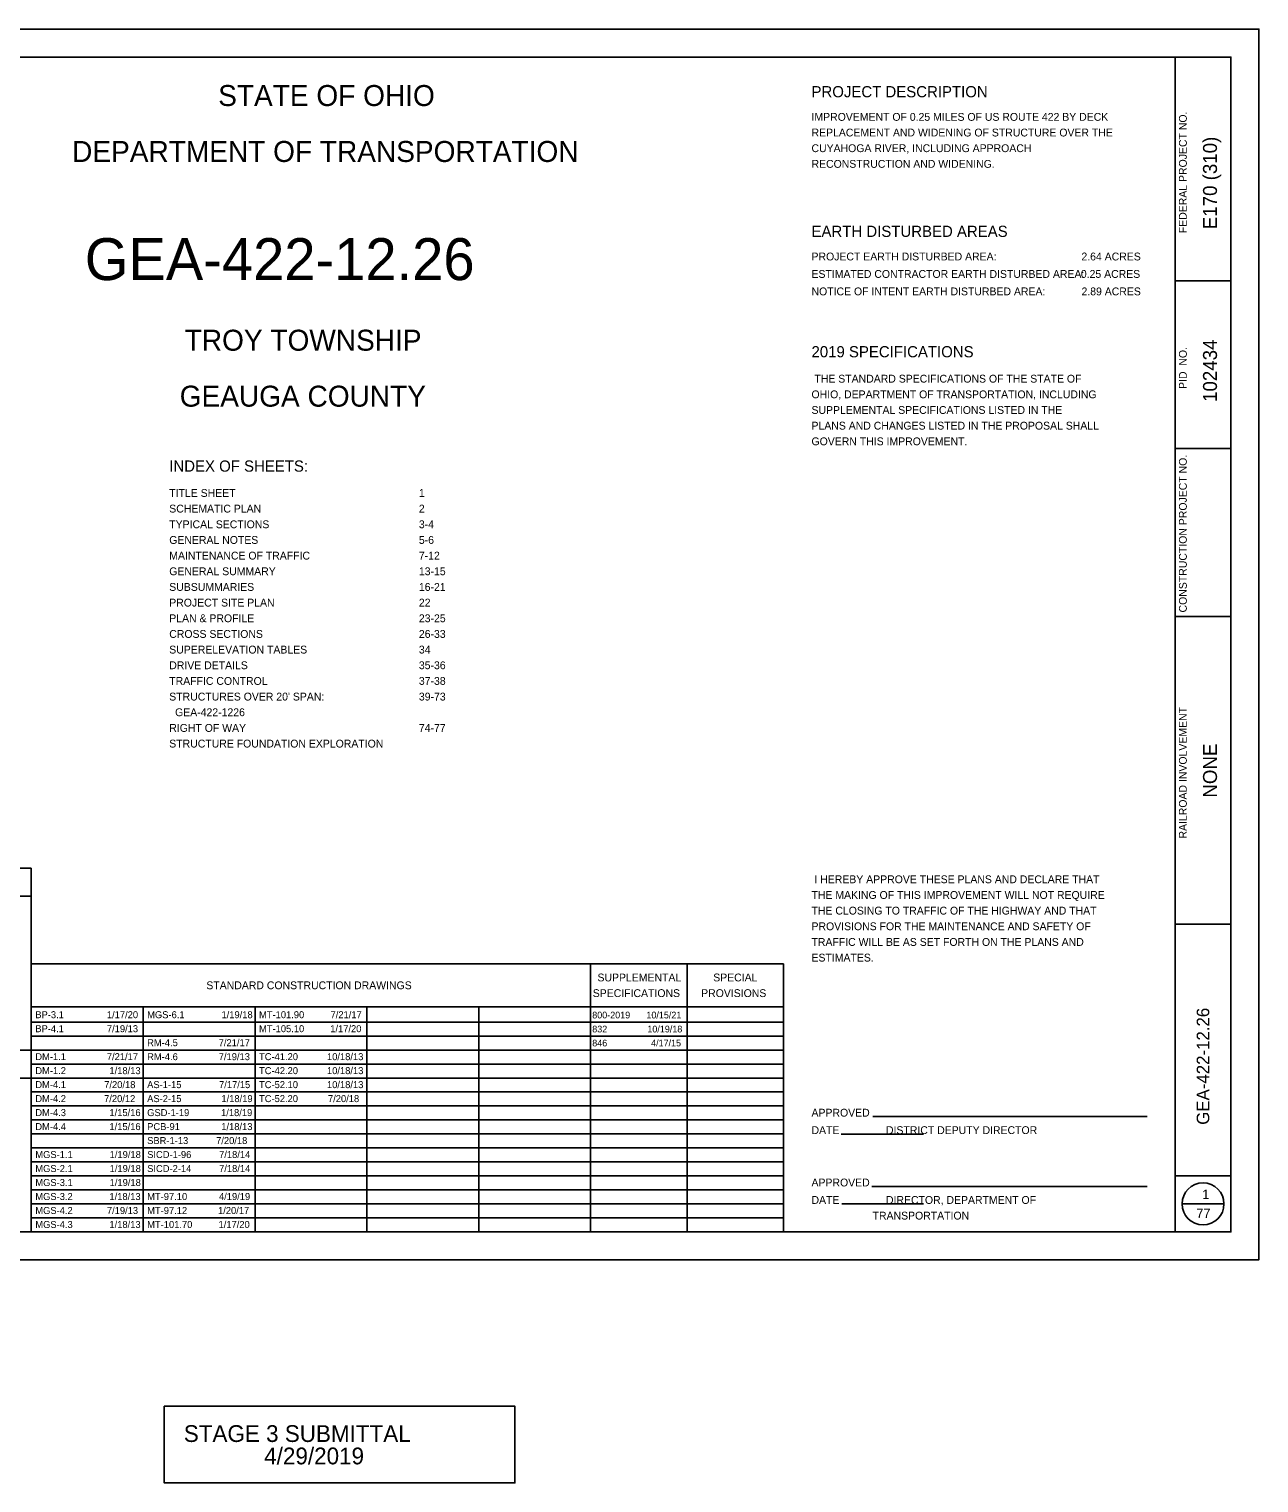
# Model space of a CAD drawing. Extents: x 10.6 to 44.6, y -2.6 to 23.4.
# Drawn here: x 22.61 to 44.6, y -2.56 to 23.43 of the extents above; entities that cross this region are included whole.
import ezdxf

# ---------------------------------------------------------------- set-up
doc = ezdxf.new("R2010")
doc.units = 0
for name, color, linetype in [('SH_Border', 7, 'Continuous'), ('SH_Cut_Line', 7, 'Continuous'), ('SH_Data', 7, 'Continuous'), ('SH_Text', 7, 'Continuous')]:
    doc.layers.add(name, color=color, linetype=linetype)

msp = doc.modelspace()

# ---------------------------------------------------------------- linework, layer by layer
at = {"layer": 'SH_Border'}
for p, q in [((43.103, 1.926), (43.103, 22.926)), ((43.103, 18.926), (44.103, 18.926)), ((43.103, 15.926), (44.103, 15.926)), ((43.103, 12.926), (44.103, 12.926)), ((43.103, 7.426), (44.103, 7.426)), ((43.103, 2.926), (44.103, 2.926))]:
    msp.add_line(p, q, dxfattribs=at)
msp.add_lwpolyline([(12.603, 22.926), (44.103, 22.926), (44.103, 1.926), (12.603, 1.926)], close=True, dxfattribs=at)
at = {"layer": 'SH_Cut_Line'}
msp.add_lwpolyline([(10.603, 1.426), (44.603, 1.426), (44.603, 23.426), (10.603, 23.426)], close=True, dxfattribs=at)
at = {"layer": 'SH_Data'}
for p, q in [((19.853, 8.426), (22.653, 8.426)), ((22.653, 1.926), (22.653, 8.426)), ((19.853, 7.926), (22.653, 7.926)), ((22.653, 6.718), (36.103, 6.718)), ((32.653, 1.926), (32.653, 6.718)), ((34.378, 1.926), (34.378, 6.718)), ((36.103, 1.926), (36.103, 6.718)), ((22.653, 5.947), (36.103, 5.947)), ((24.653, 1.926), (24.653, 5.947)), ((26.653, 1.926), (26.653, 5.947)), ((28.653, 1.926), (28.653, 5.947)), ((30.653, 1.926), (30.653, 5.947)), ((22.653, 5.676), (36.103, 5.676)), ((22.653, 5.426), (36.103, 5.426)), ((19.853, 5.176), (22.653, 5.176)), ((22.653, 5.176), (36.103, 5.176)), ((22.653, 4.926), (36.103, 4.926)), ((19.853, 4.676), (22.653, 4.676)), ((22.653, 4.676), (36.103, 4.676)), ((22.653, 4.426), (36.103, 4.426)), ((22.653, 4.176), (36.103, 4.176)), ((22.653, 3.926), (36.103, 3.926)), ((37.697, 3.986), (42.603, 3.986)), ((22.653, 3.676), (36.103, 3.676)), ((37.136, 3.674), (38.603, 3.674)), ((22.653, 3.426), (36.103, 3.426)), ((22.653, 3.176), (36.103, 3.176)), ((22.653, 2.926), (36.103, 2.926)), ((22.653, 2.676), (36.103, 2.676)), ((37.683, 2.738), (42.603, 2.738)), ((22.653, 2.426), (36.103, 2.426)), ((37.145, 2.426), (38.603, 2.426)), ((43.228, 2.426), (43.978, 2.426)), ((22.653, 2.176), (36.103, 2.176))]:
    msp.add_line(p, q, dxfattribs=at)
msp.add_circle((43.603, 2.426), 0.375, dxfattribs=at)
at = {"layer": 'SH_Text'}
msp.add_lwpolyline([(25.03, -1.193), (31.3, -1.193), (31.3, -2.562), (25.03, -2.562)], close=True, dxfattribs=at)

# ---------------------------------------------------------------- texts
at = {"layer": 'SH_Data'}
for s, height, p in [('STATE OF OHIO', 0.375, (25.995, 22.051)), ('PROJECT DESCRIPTION', 0.2, (36.603, 22.207)), ('IMPROVEMENT OF 0.25 MILES OF US ROUTE 422 BY DECK ', 0.14, (36.603, 21.787)), ('REPLACEMENT AND WIDENING OF STRUCTURE OVER THE ', 0.14, (36.603, 21.507)), ('DEPARTMENT OF TRANSPORTATION', 0.375, (23.383, 21.051)), ('CUYAHOGA RIVER, INCLUDING APPROACH ', 0.14, (36.603, 21.227)), ('RECONSTRUCTION AND WIDENING.', 0.14, (36.603, 20.947)), ('EARTH DISTURBED AREAS', 0.2, (36.603, 19.711)), ('GEA-422-12.26', 0.75, (23.61, 18.939)), ('PROJECT EARTH DISTURBED AREA:', 0.14, (36.603, 19.291)), ('2.64 ACRES', 0.14, (41.429, 19.291)), ('ESTIMATED CONTRACTOR EARTH DISTURBED AREA:', 0.14, (36.603, 18.979)), ('0.25 ACRES', 0.14, (41.419, 18.979)), ('NOTICE OF INTENT EARTH DISTURBED AREA:', 0.14, (36.603, 18.667)), ('2.89 ACRES', 0.14, (41.43, 18.667)), ('TROY TOWNSHIP', 0.375, (25.396, 17.677)), ('2019 SPECIFICATIONS', 0.2, (36.603, 17.559)), (' THE STANDARD SPECIFICATIONS OF THE STATE OF', 0.14, (36.603, 17.107)), ('GEAUGA COUNTY', 0.375, (25.307, 16.677)), ('OHIO, DEPARTMENT OF TRANSPORTATION, INCLUDING', 0.14, (36.603, 16.827)), ('SUPPLEMENTAL SPECIFICATIONS LISTED IN THE', 0.14, (36.603, 16.547)), ('PLANS AND CHANGES LISTED IN THE PROPOSAL SHALL', 0.14, (36.603, 16.267)), ('GOVERN THIS IMPROVEMENT.', 0.14, (36.603, 15.987)), ('INDEX OF SHEETS:', 0.2, (25.12, 15.515)), ('TITLE SHEET', 0.14, (25.12, 15.064)), ('SCHEMATIC PLAN', 0.14, (25.12, 14.784)), ('TYPICAL SECTIONS', 0.14, (25.12, 14.504)), ('GENERAL NOTES', 0.14, (25.12, 14.224)), ('MAINTENANCE OF TRAFFIC', 0.14, (25.12, 13.944)), ('GENERAL SUMMARY', 0.14, (25.12, 13.664)), ('SUBSUMMARIES', 0.14, (25.12, 13.384)), ('PROJECT SITE PLAN', 0.14, (25.12, 13.104)), ('PLAN & PROFILE', 0.14, (25.12, 12.824)), ('CROSS SECTIONS', 0.14, (25.12, 12.544)), ('SUPERELEVATION TABLES', 0.14, (25.12, 12.264)), ('DRIVE DETAILS', 0.14, (25.12, 11.984)), ('TRAFFIC CONTROL', 0.14, (25.12, 11.704)), ("STRUCTURES OVER 20' SPAN:", 0.14, (25.12, 11.424)), ('  GEA-422-1226', 0.14, (25.12, 11.144)), ('RIGHT OF WAY', 0.14, (25.12, 10.864)), ('STRUCTURE FOUNDATION EXPLORATION', 0.14, (25.12, 10.584)), (' I HEREBY APPROVE THESE PLANS AND DECLARE THAT ', 0.14, (36.603, 8.158)), ('THE MAKING OF THIS IMPROVEMENT WILL NOT REQUIRE', 0.14, (36.603, 7.878)), ('THE CLOSING TO TRAFFIC OF THE HIGHWAY AND THAT ', 0.14, (36.603, 7.598)), ('PROVISIONS FOR THE MAINTENANCE AND SAFETY OF ', 0.14, (36.603, 7.318)), ('TRAFFIC WILL BE AS SET FORTH ON THE PLANS AND ', 0.14, (36.603, 7.038)), ('ESTIMATES.', 0.14, (36.603, 6.758)), ('SUPPLEMENTAL', 0.14, (32.776, 6.403)), ('SPECIAL', 0.14, (34.846, 6.403)), ('STANDARD CONSTRUCTION DRAWINGS', 0.14, (25.783, 6.263)), ('SPECIFICATIONS', 0.14, (32.692, 6.123)), ('PROVISIONS', 0.14, (34.63, 6.123)), ('800-2019', 0.12, (32.683, 5.741)), ('10/15/21', 0.12, (33.651, 5.741)), ('832', 0.12, (32.683, 5.491)), ('10/19/18', 0.12, (33.668, 5.491)), ('846', 0.12, (32.683, 5.241)), ('4/17/15', 0.12, (33.735, 5.241)), ('APPROVED', 0.14, (36.603, 3.986)), ('DATE                DISTRICT DEPUTY DIRECTOR', 0.14, (36.603, 3.674)), ('APPROVED', 0.14, (36.603, 2.738)), ('1', 0.17, (43.589, 2.511)), ('DATE                DIRECTOR, DEPARTMENT OF', 0.14, (36.603, 2.426)), ('77', 0.17, (43.484, 2.171)), ('                     TRANSPORTATION', 0.14, (36.603, 2.146))]:
    msp.add_text(s, height=height, dxfattribs=at).set_placement(p)
for s, height, p in [('FEDERAL PROJECT NO.', 0.14, (43.313, 19.778)), ('E170 (310)', 0.25, (43.853, 19.849)), ('PID  NO.', 0.14, (43.313, 16.994)), ('102434', 0.25, (43.853, 16.761)), ('CONSTRUCTION PROJECT NO.', 0.14, (43.313, 12.998)), ('RAILROAD INVOLVEMENT', 0.14, (43.313, 8.957)), ('NONE', 0.25, (43.853, 9.688)), ('GEA-422-12.26', 0.225, (43.715, 3.84))]:
    msp.add_text(s, height=height, rotation=90, dxfattribs=at).set_placement(p)
at = {"layer": 'SH_Text'}
for s, height, p in [('1', 0.14, (29.583, 15.064)), ('2', 0.14, (29.583, 14.784)), ('3-4', 0.14, (29.583, 14.504)), ('5-6', 0.14, (29.583, 14.224)), ('7-12', 0.14, (29.583, 13.944)), ('13-15', 0.14, (29.583, 13.664)), ('16-21', 0.14, (29.583, 13.384)), ('22', 0.14, (29.583, 13.104)), ('23-25', 0.14, (29.583, 12.824)), ('26-33', 0.14, (29.583, 12.544)), ('34', 0.14, (29.583, 12.264)), ('35-36', 0.14, (29.583, 11.984)), ('37-38', 0.14, (29.583, 11.704)), ('39-73', 0.14, (29.583, 11.424)), ('74-77', 0.14, (29.583, 10.864)), ('BP-3.1', 0.125, (22.725, 5.745)), ('1/17/20', 0.125, (24.005, 5.745)), ('MGS-6.1', 0.125, (24.725, 5.745)), ('1/19/18', 0.125, (26.054, 5.745)), ('MT-101.90', 0.125, (26.725, 5.745)), ('7/21/17', 0.125, (28.004, 5.745)), ('BP-4.1', 0.125, (22.725, 5.495)), ('7/19/13', 0.125, (24.005, 5.495)), ('MT-105.10', 0.125, (26.725, 5.495)), ('1/17/20', 0.125, (27.998, 5.495)), ('RM-4.5', 0.125, (24.725, 5.245)), ('7/21/17', 0.125, (26.004, 5.245)), ('DM-1.1', 0.125, (22.725, 4.995)), ('7/21/17', 0.125, (24.004, 4.995)), ('RM-4.6', 0.125, (24.725, 4.995)), ('7/19/13', 0.125, (26.005, 4.995)), ('TC-41.20', 0.125, (26.725, 4.995)), ('10/18/13', 0.125, (27.94, 4.995)), ('DM-1.2', 0.125, (22.725, 4.745)), ('1/18/13', 0.125, (24.05, 4.745)), ('TC-42.20', 0.125, (26.725, 4.745)), ('10/18/13', 0.125, (27.94, 4.745)), ('DM-4.1', 0.125, (22.725, 4.495)), ('7/20/18', 0.125, (23.957, 4.495)), ('AS-1-15', 0.125, (24.725, 4.495)), ('7/17/15', 0.125, (26.01, 4.495)), ('TC-52.10', 0.125, (26.725, 4.495)), ('10/18/13', 0.125, (27.94, 4.495)), ('DM-4.2', 0.125, (22.725, 4.245)), ('7/20/12', 0.125, (23.955, 4.245)), ('AS-2-15', 0.125, (24.725, 4.245)), ('1/18/19', 0.125, (26.052, 4.245)), ('TC-52.20', 0.125, (26.725, 4.245)), ('7/20/18', 0.125, (27.958, 4.245)), ('DM-4.3', 0.125, (22.725, 3.995)), ('1/15/16', 0.125, (24.05, 3.995)), ('GSD-1-19', 0.125, (24.725, 3.995)), ('1/18/19', 0.125, (26.046, 3.995)), ('DM-4.4', 0.125, (22.725, 3.745)), ('1/15/16', 0.125, (24.05, 3.745)), ('PCB-91', 0.125, (24.725, 3.745)), ('1/18/13', 0.125, (26.05, 3.745)), ('SBR-1-13', 0.125, (24.725, 3.495)), ('7/20/18', 0.125, (25.958, 3.495)), ('MGS-1.1', 0.125, (22.725, 3.245)), ('MGS-2.1', 0.125, (22.725, 2.995)), ('1/19/18', 0.125, (24.054, 3.245)), ('1/19/18', 0.125, (24.054, 2.995)), ('SICD-1-96', 0.125, (24.725, 3.245)), ('SICD-2-14', 0.125, (24.725, 2.995)), ('7/18/14', 0.125, (26.011, 3.245)), ('7/18/14', 0.125, (26.011, 2.995)), ('MGS-3.1', 0.125, (22.725, 2.745)), ('1/19/18', 0.125, (24.054, 2.745)), ('MGS-3.2', 0.125, (22.725, 2.495)), ('1/18/13', 0.125, (24.05, 2.495)), ('MT-97.10', 0.125, (24.725, 2.495)), ('4/19/19', 0.125, (26.009, 2.495)), ('MGS-4.2', 0.125, (22.725, 2.245)), ('7/19/13', 0.125, (24.005, 2.245)), ('MT-97.12', 0.125, (24.725, 2.245)), ('1/20/17', 0.125, (25.992, 2.245)), ('MGS-4.3', 0.125, (22.725, 1.995)), ('1/18/13', 0.125, (24.05, 1.995)), ('MT-101.70', 0.125, (24.725, 1.995)), ('1/17/20', 0.125, (26.001, 1.995)), ('STAGE 3 SUBMITTAL', 0.3, (25.38, -1.83)), ('4/29/2019', 0.3, (26.818, -2.23))]:
    msp.add_text(s, height=height, dxfattribs=at).set_placement(p)

doc.saveas('drawing.dxf')
